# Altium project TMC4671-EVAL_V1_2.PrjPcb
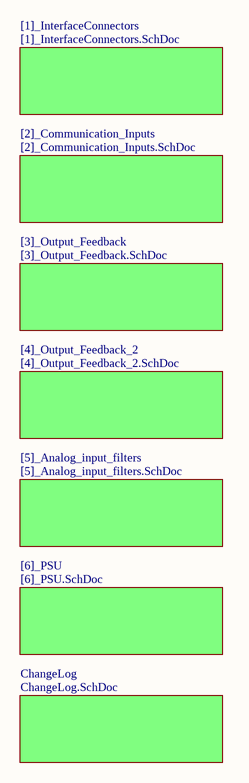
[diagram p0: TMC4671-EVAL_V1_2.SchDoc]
Interfaces: SPI, UART, S/D; Chip: TMCxxx; BoardVersion: 1.2; BoardName: TMC4671-EVAL
8 sheets, 149 parts. Net scope: flat (ports and power ports of the same name join across sheets).
Board file: TMC4671-EVAL_V1_2.PcbDoc
Sheets:
  TMC4671-EVAL_V1_2.SchDoc
    ChangeLog = ChangeLog.SchDoc
    [1]_InterfaceConnectors = [1]_InterfaceConnectors.SchDoc
    [2]_Communication_Inputs = [2]_Communication_Inputs.SchDoc
    [3]_Output_Feedback = [3]_Output_Feedback.SchDoc
    [4]_Output_Feedback_2 = [4]_Output_Feedback_2.SchDoc
    [5]_Analog_input_filters = [5]_Analog_input_filters.SchDoc
    [6]_PSU = [6]_PSU.SchDoc

## Sheet TMC4671-EVAL_V1_2.SchDoc: TMC4671_EVAL_V1.0
size A4; DocumentNumber: 0; SheetNumber: 0; SheetTotal: 8

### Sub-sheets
[1]_InterfaceConnectors = [1]_InterfaceConnectors.SchDoc: no entries
[2]_Communication_Inputs = [2]_Communication_Inputs.SchDoc: no entries
[3]_Output_Feedback = [3]_Output_Feedback.SchDoc: no entries
[4]_Output_Feedback_2 = [4]_Output_Feedback_2.SchDoc: no entries
[5]_Analog_input_filters = [5]_Analog_input_filters.SchDoc: no entries
[6]_PSU = [6]_PSU.SchDoc: no entries
ChangeLog = ChangeLog.SchDoc: no entries

## Sheet ChangeLog.SchDoc: ChangeLog
size A4; DocumentNumber: 7; SheetNumber: 7; SheetTotal: 8
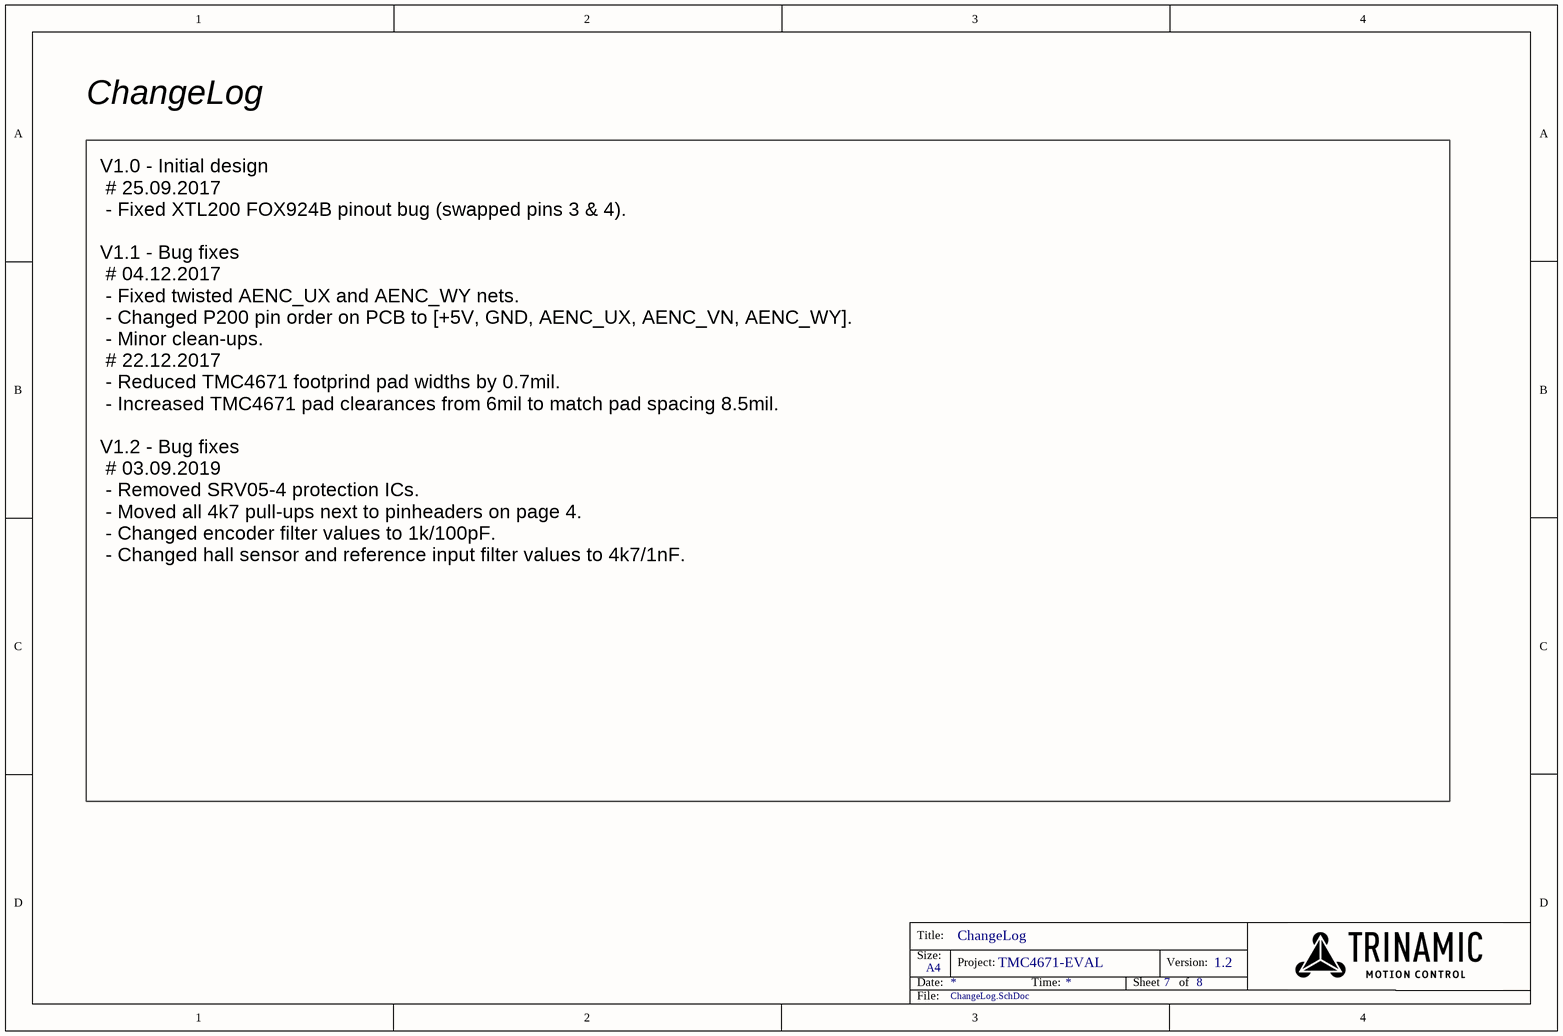
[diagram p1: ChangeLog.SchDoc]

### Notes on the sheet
- ChangeLog
- V1.0 - Initial design
  # 25.09.2017
  - Fixed XTL200 FOX924B pinout bug (swapped pins 3 & 4).
  V1.1 - Bug fixes
  # 04.12.2017
  - Fixed twisted AENC_UX and AENC_WY nets.
  - Changed P200 pin order on PCB to [+5V, GND, AENC_UX, AENC_VN, AENC_WY].
  - Minor clean-ups.
  # 22.12.2017
  - Reduced TMC4671 footprind pad widths by 0.7mil.
  - Increased TMC4671 pad clearances from 6mil to match pad spacing 8.5mil.
  V1.2 - Bug fixes
  # 03.09.2019
  - Removed SRV05-4 protection ICs.
  - Moved all 4k7 pull-ups next to pinheaders on page 4.
  - Changed encoder filter values to 1k/100pF.
  - Changed hall sensor and reference input filter values to 4k7/1nF.

## Sheet [1]_InterfaceConnectors.SchDoc: Interface connectors, mounting holes & testpads
size A4; DocumentNumber: 1; SheetNumber: 1; SheetTotal: 8
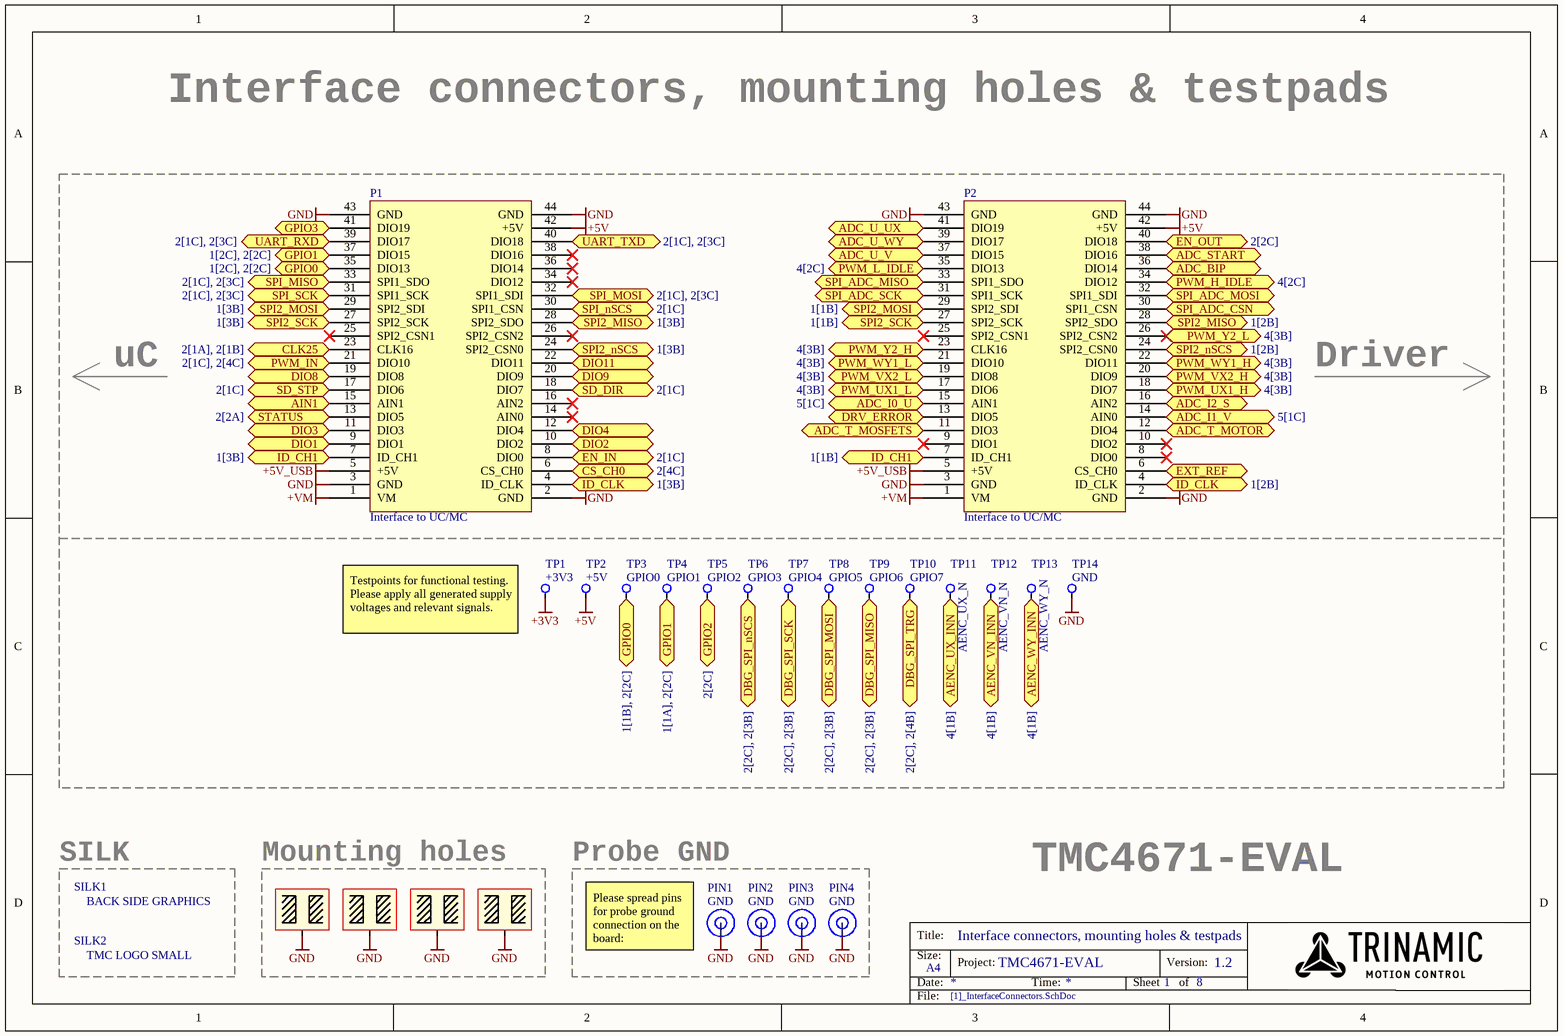
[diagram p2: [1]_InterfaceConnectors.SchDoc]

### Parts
MNT1  MOUNTING_HOLE  [MNT_HOLE_6.35-3.2]  (value not drawn)  (no BOM)
MNT2  MOUNTING_HOLE  [MNT_HOLE_6.35-3.2]  (value not drawn)  (no BOM)
MNT3  MOUNTING_HOLE  [MNT_HOLE_6.35-3.2]  (value not drawn)  (no BOM)
MNT4  MOUNTING_HOLE  [MNT_HOLE_6.35-3.2]  (value not drawn)  (no BOM)
P1  Interface to UC/MC  [Interface_Connector]
P2  Interface to UC/MC  [Interface_Connector]
PIN1  GND  [TP_1.1-1.85_OCT]  (no BOM)
PIN2  GND  [TP_1.1-1.85_OCT]  (no BOM)
PIN3  GND  [TP_1.1-1.85_OCT]  (no BOM)
PIN4  GND  [TP_1.1-1.85_OCT]  (no BOM)
SILK1  BACK SIDE GRAPHICS  [TMC4671_EVAL_v1_0_back_label]  (no BOM)
SILK2  TMC LOGO SMALL  [TMC_logo_small]  (no BOM)
TP1  +3V3  [TP_SMD_1.2MM_ROUND]  (no BOM)
TP2  +5V  [TP_SMD_1.2MM_ROUND]  (no BOM)
TP3  GPIO0  [TP_SMD_1.2MM_ROUND]  (no BOM)
TP4  GPIO1  [TP_SMD_1.2MM_ROUND]  (no BOM)
TP5  GPIO2  [TP_SMD_1.2MM_ROUND]  (no BOM)
TP6  GPIO3  [TP_SMD_1.2MM_ROUND]  (no BOM)
TP7  GPIO4  [TP_SMD_1.2MM_ROUND]  (no BOM)
TP8  GPIO5  [TP_SMD_1.2MM_ROUND]  (no BOM)
TP9  GPIO6  [TP_SMD_1.2MM_ROUND]  (no BOM)
TP10  GPIO7  [TP_SMD_1.2MM_ROUND]  (no BOM)
TP11  AENC_UX_N  [TP_SMD_1.2MM_ROUND]  (no BOM)
TP12  AENC_VN_N  [TP_SMD_1.2MM_ROUND]  (no BOM)
TP13  AENC_WY_N  [TP_SMD_1.2MM_ROUND]  (no BOM)
TP14  GND  [TP_SMD_1.2MM_ROUND]  (no BOM)

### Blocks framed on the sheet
SILK: SILK1 SILK2
Mounting holes: MNT1-MNT4
Probe GND: PIN1-PIN4

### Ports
ADC_BIP, ADC_I0_U (see 5[1C]), ADC_I1_V (see 5[1C]), ADC_I2_S, ADC_START, ADC_T_MOSFETS, ADC_T_MOTOR, ADC_U_UX, ADC_U_V, ADC_U_WY, AENC_UX_INN (see 4[1B]), AENC_VN_INN (see 4[1B]), AENC_WY_INN (see 4[1B]), AIN1, CLK25 (see 2[1A], 2[1B]), CS_CH0 (see 2[4C]), DBG_SPI_MISO (see 2[2C], 2[3B]), DBG_SPI_MOSI (see 2[2C], 2[3B]), DBG_SPI_nSCS (see 2[2C], 2[3B]), DBG_SPI_SCK (see 2[2C], 2[3B]), DBG_SPI_TRG (see 2[2C], 2[4B]), DIO1, DIO2, DIO3, DIO4, DIO8, DIO9, DIO11, DRV_ERROR, EN_IN (see 2[1C]), EN_OUT (see 2[2C]), EXT_REF, GPIO0 (see 1[1B], 2[2C]), GPIO0 (see 1[2C], 2[2C]), GPIO1 (see 1[1A], 2[2C]), GPIO1 (see 1[2C], 2[2C]), GPIO2 (see 2[2C]), GPIO3, ID_CH1 (see 1[1B]), ID_CH1 (see 1[3B]), ID_CLK (see 1[2B]), ID_CLK (see 1[3B]), PWM_H_IDLE (see 4[2C]), PWM_IN (see 2[1C], 2[4C]), PWM_L_IDLE (see 4[2C]), PWM_UX1_H (see 4[3B]), PWM_UX1_L (see 4[3B]), PWM_VX2_H (see 4[3B]), PWM_VX2_L (see 4[3B]), PWM_WY1_H (see 4[3B]), PWM_WY1_L (see 4[3B]), PWM_Y2_H (see 4[3B]), PWM_Y2_L (see 4[3B]), SD_DIR (see 2[1C]), SD_STP (see 2[1C]), SPI2_MISO (see 1[2B]), SPI2_MISO (see 1[3B]), SPI2_MOSI (see 1[1B]), SPI2_MOSI (see 1[3B]), SPI2_nSCS (see 1[2B]), SPI2_nSCS (see 1[3B]), SPI2_SCK (see 1[1B]), SPI2_SCK (see 1[3B]), SPI_ADC_CSN, SPI_ADC_MISO, SPI_ADC_MOSI, SPI_ADC_SCK, SPI_MISO (see 2[1C], 2[3C]), SPI_MOSI (see 2[1C], 2[3C]), SPI_nSCS (see 2[1C]), SPI_SCK (see 2[1C], 2[3C]), STATUS (see 2[2A]), UART_RXD (see 2[1C], 2[3C]), UART_TXD (see 2[1C], 2[3C])

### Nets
+3V3: TP1.1
+5V: P1.42(+5V) P2.42(+5V) TP2.1
+5V_USB: P1.5(+5V) P2.5(+5V)
+VM: P1.1(VM) P2.1(VM)
GND: MNT1.1 MNT2.1 MNT3.1 MNT4.1 P1.2(GND) P1.3(GND) P1.43(GND) P1.44(GND) P2.2(GND) P2.3(GND) P2.43(GND) P2.44(GND) PIN1.1 PIN2.1 PIN3.1 PIN4.1 TP14.1
ADC_BIP: P2.36(DIO14) ; port ADC_BIP
ADC_I0_U: P2.15(AIN1) ; port ADC_I0_U
ADC_I1_V: P2.14(AIN0) ; port ADC_I1_V
ADC_I2_S: P2.16(AIN2) ; port ADC_I2_S
ADC_START: P2.38(DIO16) ; port ADC_START
ADC_T_MOSFETS: P2.11(DIO3) ; port ADC_T_MOSFETS
ADC_T_MOTOR: P2.12(DIO4) ; port ADC_T_MOTOR
ADC_U_UX: P2.41(DIO19) ; port ADC_U_UX
ADC_U_V: P2.37(DIO15) ; port ADC_U_V
ADC_U_WY: P2.39(DIO17) ; port ADC_U_WY
AENC_UX_INN: TP11.1 ; port AENC_UX_INN
AENC_VN_INN: TP12.1 ; port AENC_VN_INN
AENC_WY_INN: TP13.1 ; port AENC_WY_INN
AIN1: P1.15(AIN1) ; port AIN1
CLK25: P1.23(CLK16) ; port CLK25
CS_CH0: P1.6(CS_CH0) ; port CS_CH0
DBG_SPI_MISO: TP9.1 ; port DBG_SPI_MISO
DBG_SPI_MOSI: TP8.1 ; port DBG_SPI_MOSI
DBG_SPI_nSCS: TP6.1 ; port DBG_SPI_nSCS
DBG_SPI_SCK: TP7.1 ; port DBG_SPI_SCK
DBG_SPI_TRG: TP10.1 ; port DBG_SPI_TRG
DIO1: P1.9(DIO1) ; port DIO1
DIO2: P1.10(DIO2) ; port DIO2
DIO3: P1.11(DIO3) ; port DIO3
DIO4: P1.12(DIO4) ; port DIO4
DIO8: P1.19(DIO8) ; port DIO8
DIO9: P1.20(DIO9) ; port DIO9
DIO11: P1.22(DIO11) ; port DIO11
DRV_ERROR: P2.13(DIO5) ; port DRV_ERROR
EN_IN: P1.8(DIO0) ; port EN_IN
EN_OUT: P2.40(DIO18) ; port EN_OUT
EXT_REF: P2.6(CS_CH0) ; port EXT_REF
GPIO0: P1.35(DIO13) TP3.1 ; port GPIO0
GPIO1: P1.37(DIO15) TP4.1 ; port GPIO1
GPIO2: TP5.1 ; port GPIO2
GPIO3: P1.41(DIO19) ; port GPIO3
ID_CH1: P1.7(ID_CH1) P2.7(ID_CH1) ; port ID_CH1
ID_CLK: P1.4(ID_CLK) P2.4(ID_CLK) ; port ID_CLK
PWM_H_IDLE: P2.34(DIO12) ; port PWM_H_IDLE
PWM_IN: P1.21(DIO10) ; port PWM_IN
PWM_L_IDLE: P2.35(DIO13) ; port PWM_L_IDLE
PWM_UX1_H: P2.18(DIO7) ; port PWM_UX1_H
PWM_UX1_L: P2.17(DIO6) ; port PWM_UX1_L
PWM_VX2_H: P2.20(DIO9) ; port PWM_VX2_H
PWM_VX2_L: P2.19(DIO8) ; port PWM_VX2_L
PWM_WY1_H: P2.22(DIO11) ; port PWM_WY1_H
PWM_WY1_L: P2.21(DIO10) ; port PWM_WY1_L
PWM_Y2_H: P2.23(CLK16) ; port PWM_Y2_H
PWM_Y2_L: P2.26(SPI2_CSN2) ; port PWM_Y2_L
SD_DIR: P1.18(DIO7) ; port SD_DIR
SD_STP: P1.17(DIO6) ; port SD_STP
SPI2_MISO: P1.28(SPI2_SDO) P2.28(SPI2_SDO) ; port SPI2_MISO
SPI2_MOSI: P1.29(SPI2_SDI) P2.29(SPI2_SDI) ; port SPI2_MOSI
SPI2_nSCS: P1.24(SPI2_CSN0) P2.24(SPI2_CSN0) ; port SPI2_nSCS
SPI2_SCK: P1.27(SPI2_SCK) P2.27(SPI2_SCK) ; port SPI2_SCK
SPI_ADC_CSN: P2.30(SPI1_CSN) ; port SPI_ADC_CSN
SPI_ADC_MISO: P2.33(SPI1_SDO) ; port SPI_ADC_MISO
SPI_ADC_MOSI: P2.32(SPI1_SDI) ; port SPI_ADC_MOSI
SPI_ADC_SCK: P2.31(SPI1_SCK) ; port SPI_ADC_SCK
SPI_MISO: P1.33(SPI1_SDO) ; port SPI_MISO
SPI_MOSI: P1.32(SPI1_SDI) ; port SPI_MOSI
SPI_nSCS: P1.30(SPI1_CSN) ; port SPI_nSCS
SPI_SCK: P1.31(SPI1_SCK) ; port SPI_SCK
STATUS: P1.13(DIO5) ; port STATUS
UART_RXD: P1.39(DIO17) ; port UART_RXD
UART_TXD: P1.40(DIO18) ; port UART_TXD

Not connected (* = marked no-connect by the designer): P1 14(AIN0)* 16(AIN2)* 25(SPI2_CSN1)* 26(SPI2_CSN2)* 34(DIO12)* 36(DIO14)* 38(DIO16)*; P2 8(DIO0)* 9(DIO1)* 10(DIO2)* 25(SPI2_CSN1)*

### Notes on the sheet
- uC
- Driver
- (near TP1) Testpoints for functional testing.
  Please apply all generated supply voltages and relevant signals.
- (near PIN1) Please spread pins for probe ground connection on the board:

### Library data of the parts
P1 P2 = Interface Connector, 44 Pins: Board-To-Board Connector, 2.54 mm, 44 Contacts, Receptacle, HLE Series, Surface Mount, 2 Rows; MPN: HLE-122-02-L-DV; MF: SAMTEC
PIN1-PIN4 = TP_1.1-1.85_OCT: TH testpoint, 1.1 hole, 1.85 pad, octagonal
SILK1 SILK2 = SILK_GFX
TP1-TP14 = TP_SMD_Xmm: SMD testpoint, 1.2mm pad, round

## Sheet [2]_Communication_Inputs.SchDoc: Communication & Inputs
size A4; DocumentNumber: 2; SheetNumber: 2; SheetTotal: 8
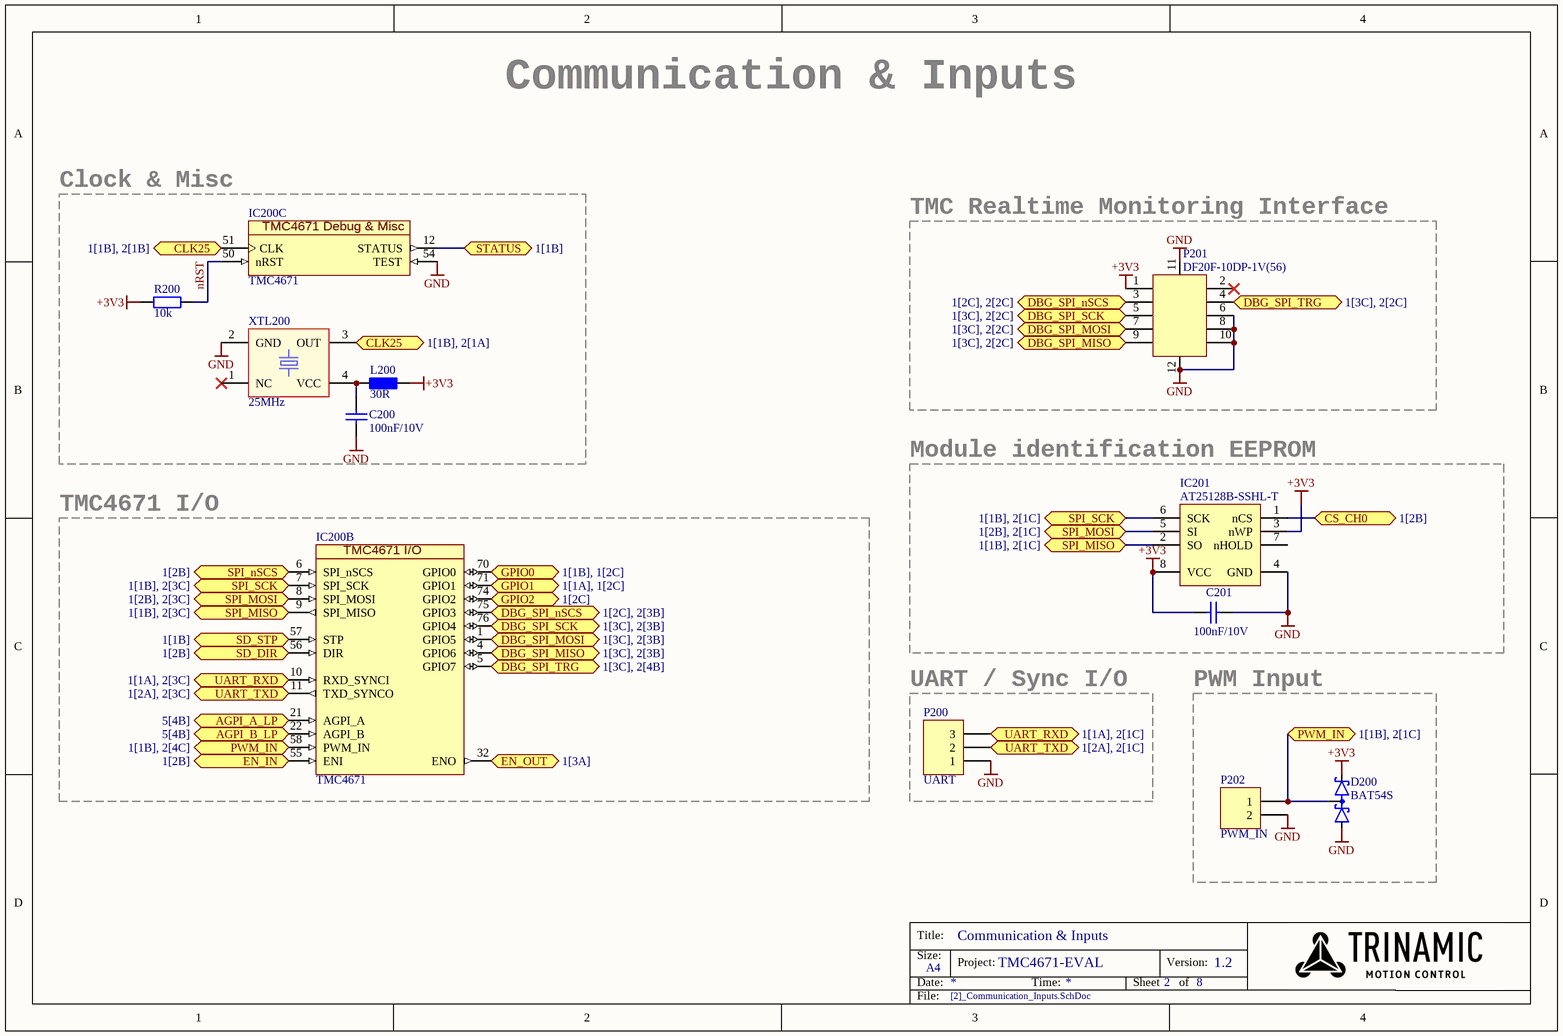
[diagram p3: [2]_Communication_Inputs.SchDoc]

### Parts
C200  100nF/10V  [C0603]
C201  100nF/10V  [C0603]
D200  BAT54S  [SOT95P237X130-3N]
IC200  TMC4671  [QFN40P1050X650X90_HS-77N]  (parts B,C of 5)
IC201  AT25128B-SSHL-T  [SOP127P600X175-8N]
L200  30R  [L0603]
P200  UART  [TH_HDR_1X3]
P201  DF20F-10DP-1V(56)  [CON, TMC Debug SPI]
P202  PWM_IN  [TH_HDR_1X2]
R200  10k  [R0603]
XTL200  25MHz  [FOX924B-25.000]

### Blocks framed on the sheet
Clock & Misc: C200 IC200 L200 R200 XTL200
TMC Realtime Monitoring Interface: P201
TMC4671 I/O: IC200
Module identification EEPROM: C201 IC201
UART / Sync I/O: P200
PWM Input: D200 P202

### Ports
AGPI_A_LP (see 5[4B]), AGPI_B_LP (see 5[4B]), CLK25 (see 1[1B], 2[1A]), CLK25 (see 1[1B], 2[1B]), CS_CH0 (see 1[2B]), DBG_SPI_MISO (see 1[3C], 2[2C]), DBG_SPI_MISO (see 1[3C], 2[3B]), DBG_SPI_MOSI (see 1[3C], 2[2C]), DBG_SPI_MOSI (see 1[3C], 2[3B]), DBG_SPI_nSCS (see 1[2C], 2[2C]), DBG_SPI_nSCS (see 1[2C], 2[3B]), DBG_SPI_SCK (see 1[3C], 2[2C]), DBG_SPI_SCK (see 1[3C], 2[3B]), DBG_SPI_TRG (see 1[3C], 2[2C]), DBG_SPI_TRG (see 1[3C], 2[4B]), EN_IN (see 1[2B]), EN_OUT (see 1[3A]), GPIO0 (see 1[1B], 1[2C]), GPIO1 (see 1[1A], 1[2C]), GPIO2 (see 1[2C]), PWM_IN (see 1[1B], 2[1C]), PWM_IN (see 1[1B], 2[4C]), SD_DIR (see 1[2B]), SD_STP (see 1[1B]), SPI_MISO (see 1[1B], 2[1C]), SPI_MISO (see 1[1B], 2[3C]), SPI_MOSI (see 1[2B], 2[1C]), SPI_MOSI (see 1[2B], 2[3C]), SPI_nSCS (see 1[2B]), SPI_SCK (see 1[1B], 2[1C]), SPI_SCK (see 1[1B], 2[3C]), STATUS (see 1[1B]), UART_RXD (see 1[1A], 2[1C]), UART_RXD (see 1[1A], 2[3C]), UART_TXD (see 1[2A], 2[1C]), UART_TXD (see 1[2A], 2[3C])

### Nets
+3V3: C201.2 D200.2(C2) IC201.3(nWP) IC201.8(VCC) L200.1 P201.1 R200.2
GND: C200.2 C201.1 D200.1(A1) IC200.54(TEST) IC201.4(GND) P200.1 P201.6 P201.8 P201.10 P201.11 P201.12 P202.2 XTL200.2(GND)
AGPI_A_LP: IC200.21(AGPI_A) ; port AGPI_A_LP
AGPI_B_LP: IC200.22(AGPI_B) ; port AGPI_B_LP
CLK25: IC200.51(CLK) XTL200.3(OUT) ; port CLK25
CS_CH0: IC201.1(nCS) ; port CS_CH0
DBG_SPI_MISO: IC200.4(GPIO6) P201.9 ; port DBG_SPI_MISO
DBG_SPI_MOSI: IC200.1(GPIO5) P201.7 ; port DBG_SPI_MOSI
DBG_SPI_nSCS: IC200.75(GPIO3) P201.3 ; port DBG_SPI_nSCS
DBG_SPI_SCK: IC200.76(GPIO4) P201.5 ; port DBG_SPI_SCK
DBG_SPI_TRG: IC200.5(GPIO7) P201.4 ; port DBG_SPI_TRG
EN_IN: IC200.55(ENI) ; port EN_IN
EN_OUT: IC200.32(ENO) ; port EN_OUT
GPIO0: IC200.70(GPIO0) ; port GPIO0
GPIO1: IC200.71(GPIO1) ; port GPIO1
GPIO2: IC200.74(GPIO2) ; port GPIO2
nRST: IC200.50(nRST) R200.1
PWM_IN: D200.3(C1A2) IC200.58(PWM_IN) P202.1 ; port PWM_IN
SD_DIR: IC200.56(DIR) ; port SD_DIR
SD_STP: IC200.57(STP) ; port SD_STP
SPI_MISO: IC200.9(SPI_MISO) IC201.2(SO) ; port SPI_MISO
SPI_MOSI: IC200.8(SPI_MOSI) IC201.5(SI) ; port SPI_MOSI
SPI_nSCS: IC200.6(SPI_nSCS) ; port SPI_nSCS
SPI_SCK: IC200.7(SPI_SCK) IC201.6(SCK) ; port SPI_SCK
STATUS: IC200.12(STATUS) ; port STATUS
UART_RXD: IC200.10(RXD_SYNCI) P200.3 ; port UART_RXD
UART_TXD: IC200.11(TXD_SYNCO) P200.2 ; port UART_TXD
NetC200_1: C200.1 L200.2 XTL200.4(VCC)

Not connected (* = marked no-connect by the designer): IC201 7(nHOLD); P201 2*; XTL200 1(NC)*

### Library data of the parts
C200 C201 = C, 0.1 µF, 10 V, ± 10%, X7R, 0603: SMD Multilayer Ceramic Capacitor, 0603 [1608 Metric], 0.1 µF, 10 V, ± 10%, X7R, MC Series; MPN: MC0603B104K100CT; Type: MLCC; VoltageRating: 10V; MF: Multicomp; Capacitance: 100nF
D200 = BAT54S: Small Signal Schottky Diode, Dual Series, 30 V, 200 mA, 1 V, 600 mA, 125 °C; MF: TAIWAN SEMICONDUCTOR
IC200 = TMC4671: MF: TRINAMIC
IC201 = EEPROM_ AT25128B-SSHL-T: EEPROM, SPI, 128 Kbit, 16K x 8bit, 20 MHz, SOIC, 8 Pins; MF: MICROCHIP
L200 = FB, 30 ohm, 0603 [1608 Metric], MFB Series, 3 A, 0.04 ohm, ± 25%: Ferrite Bead, 30 ohm, 0603 [1608 Metric], MFB Series, 3 A, 0.04 ohm, ± 25%; MPN: MFB-160808-0030PQ; MF: MEC MARCOM; DC Current Rating: 3A; DC Resistance Max:: 0R04
P200 = Header 3: Header, 3-Pin; Note: Not fitted
P201 = CON, TMC Debug SPI: Wire-To-Board Connector, 1 mm, 10 Contacts, Header, DF20 Series, Surface Mount, 2 Rows; MF: Hirose Electric Co Ltd
P202 = Header 2: Header, 2-Pin; Note: Not fitted
R200 = R, 10 kohm, 50 V, 0603 [1608 Metric], 63 mW, ± 1%, MC Series: SMD Chip Resistor, Thick Film, 10 kohm, 50 V, 0603 [1608 Metric], 63 mW, ± 1%, MC Series; MPN: MC0063W0603110K; VoltageRating: 50V; Temp coefficient: *ppm; PowerRating: 63mW; MF: MULTICOMP
XTL200 = 25 MHz, 2.5 ppm, SMD, 5mm x 3.2mm, HCMOS, 3.3 V, FOX924 Series: TCXO, 25 MHz, 2.5 ppm, SMD, 5mm x 3.2mm, HCMOS, 3.3 V, FOX924 Series; MF: FOX ELECTRONICS; Freq. Stability: 2.5ppm; Op.temp.: -30°C...+80°C

## Sheet [3]_Output_Feedback.SchDoc: Output & Feedback
size A4 portrait; DocumentNumber: 3; SheetNumber: 3; SheetTotal: 8
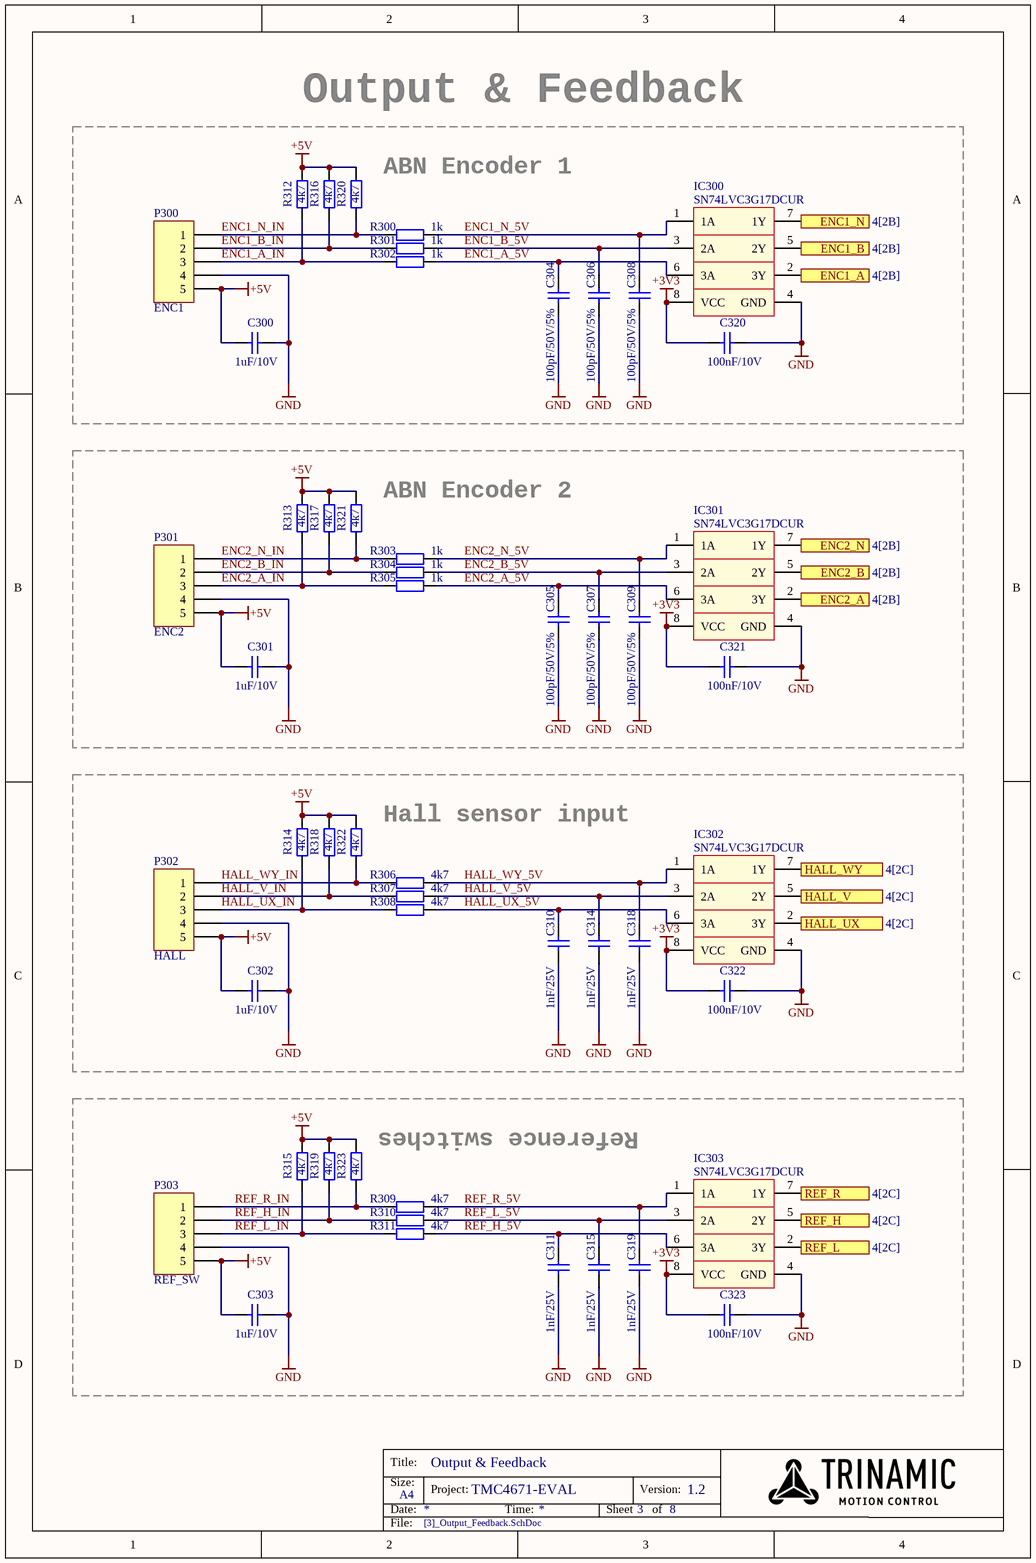
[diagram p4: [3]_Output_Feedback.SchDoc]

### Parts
C300  1uF/10V  [C0603]
C301  1uF/10V  [C0603]
C302  1uF/10V  [C0603]
C303  1uF/10V  [C0603]
C304  100pF/50V/5%  [C0603]
C305  100pF/50V/5%  [C0603]
C306  100pF/50V/5%  [C0603]
C307  100pF/50V/5%  [C0603]
C308  100pF/50V/5%  [C0603]
C309  100pF/50V/5%  [C0603]
C310  1nF/25V  [C0603]
C311  1nF/25V  [C0603]
C314  1nF/25V  [C0603]
C315  1nF/25V  [C0603]
C318  1nF/25V  [C0603]
C319  1nF/25V  [C0603]
C320  100nF/10V  [C0603]
C321  100nF/10V  [C0603]
C322  100nF/10V  [C0603]
C323  100nF/10V  [C0603]
IC300  SN74LVC3G17DCUR  [TSSOP50P310X90-8L]
IC301  SN74LVC3G17DCUR  [TSSOP50P310X90-8L]
IC302  SN74LVC3G17DCUR  [TSSOP50P310X90-8L]
IC303  SN74LVC3G17DCUR  [TSSOP50P310X90-8L]
P300  ENC1  [TH_HDR_1X5]
P301  ENC2  [TH_HDR_1X5]
P302  HALL  [TH_HDR_1X5]
P303  REF_SW  [TH_HDR_1X5]
R300  1k  [R0603]
R301  1k  [R0603]
R302  1k  [R0603]
R303  1k  [R0603]
R304  1k  [R0603]
R305  1k  [R0603]
R306  4k7  [R0603]
R307  4k7  [R0603]
R308  4k7  [R0603]
R309  4k7  [R0603]
R310  4k7  [R0603]
R311  4k7  [R0603]
R312  4k7  [R0603]
R313  4k7  [R0603]
R314  4k7  [R0603]
R315  4k7  [R0603]
R316  4k7  [R0603]
R317  4k7  [R0603]
R318  4k7  [R0603]
R319  4k7  [R0603]
R320  4k7  [R0603]
R321  4k7  [R0603]
R322  4k7  [R0603]
R323  4k7  [R0603]

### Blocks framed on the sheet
ABN Encoder 1: C300 C304 C306 C308 C320 IC300 P300 R300-R302 R312 R316 R320
ABN Encoder 2: C301 C305 C307 C309 C321 IC301 P301 R303-R305 R313 R317 R321
Hall sensor input: C302 C310 C314 C318 C322 IC302 P302 R306-R308 R314 R318 R322
Reference switches: C303 C311 C315 C319 C323 IC303 P303 R309-R311 R315 R319 R323

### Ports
ENC1_A (see 4[2B]), ENC1_B (see 4[2B]), ENC1_N (see 4[2B]), ENC2_A (see 4[2B]), ENC2_B (see 4[2B]), ENC2_N (see 4[2B]), HALL_UX (see 4[2C]), HALL_V (see 4[2C]), HALL_WY (see 4[2C]), REF_H (see 4[2C]), REF_L (see 4[2C]), REF_R (see 4[2C])

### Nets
+3V3: C320.2 C321.2 C322.2 C323.2 IC300.8(VCC) IC301.8(VCC) IC302.8(VCC) IC303.8(VCC)
+5V: C300.2 C301.2 C302.2 C303.2 P300.5 P301.5 P302.5 P303.5 R312.2 R313.2 R314.2 R315.2 R316.2 R317.2 R318.2 R319.2 R320.2 R321.2 R322.2 R323.2
GND: C300.1 C301.1 C302.1 C303.1 C304.1 C305.1 C306.1 C307.1 C308.1 C309.1 C310.1 C311.1 C314.1 C315.1 C318.1 C319.1 C320.1 C321.1 C322.1 C323.1 IC300.4(GND) IC301.4(GND) IC302.4(GND) IC303.4(GND) P300.4 P301.4 P302.4 P303.4
ENC1_A: IC300.2(3Y) ; port ENC1_A
ENC1_A_5V: C304.2 IC300.6(3A) R302.2
ENC1_A_IN: P300.3 R302.1 R312.1
ENC1_B: IC300.5(2Y) ; port ENC1_B
ENC1_B_5V: C306.2 IC300.3(2A) R301.2
ENC1_B_IN: P300.2 R301.1 R316.1
ENC1_N: IC300.7(1Y) ; port ENC1_N
ENC1_N_5V: C308.2 IC300.1(1A) R300.2
ENC1_N_IN: P300.1 R300.1 R320.1
ENC2_A: IC301.2(3Y) ; port ENC2_A
ENC2_A_5V: C305.2 IC301.6(3A) R305.2
ENC2_A_IN: P301.3 R305.1 R313.1
ENC2_B: IC301.5(2Y) ; port ENC2_B
ENC2_B_5V: C307.2 IC301.3(2A) R304.2
ENC2_B_IN: P301.2 R304.1 R317.1
ENC2_N: IC301.7(1Y) ; port ENC2_N
ENC2_N_5V: C309.2 IC301.1(1A) R303.2
ENC2_N_IN: P301.1 R303.1 R321.1
HALL_UX: IC302.2(3Y) ; port HALL_UX
HALL_UX_5V: C310.2 IC302.6(3A) R308.1
HALL_UX_IN: P302.3 R308.2 R314.1
HALL_V: IC302.5(2Y) ; port HALL_V
HALL_V_5V: C314.2 IC302.3(2A) R307.1
HALL_V_IN: P302.2 R307.2 R318.1
HALL_WY: IC302.7(1Y) ; port HALL_WY
HALL_WY_5V: C318.2 IC302.1(1A) R306.1
HALL_WY_IN: P302.1 R306.2 R322.1
REF_H: IC303.5(2Y) ; port REF_H
REF_H_5V: C311.2 IC303.6(3A) R311.1
REF_H_IN: P303.2 R310.2 R319.1
REF_L: IC303.2(3Y) ; port REF_L
REF_L_5V: C315.2 IC303.3(2A) R310.1
REF_L_IN: P303.3 R311.2 R315.1
REF_R: IC303.7(1Y) ; port REF_R
REF_R_5V: C319.2 IC303.1(1A) R309.1
REF_R_IN: P303.1 R309.2 R323.1

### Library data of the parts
C300-C303 = C, 1 µF, 10 V, ± 10%, X5R, MC Series, 0603 [1608 Metric]: SMD Multilayer Ceramic Capacitor, 0603 [1608 Metric], 1 µF, 10 V, ± 10%, X5R, MC Series; MPN: MC0603X105K100CT; Type: MLCC; VoltageRating: 10V; MF: MULTICOMP; Capacitance: 1uF
C304-C309 = C, 100 pF, 50 V, ± 5%, C0G / NP0, MC Series, 0603 [1608 Metric]: SMD Multilayer Ceramic Capacitor, 0603 [1608 Metric], 100 pF, 50 V, ± 5%, C0G / NP0, MC Series; MPN: MC0603N101J500CT; Type: MLCC; VoltageRating: 50V; MF: MULTICOMP; Capacitance: 100pF
C310 C311 C314 C315 C318 C319 = C, 1nF, 25 V, ± 10%, X7R, MC Series, 0603 [1608 Metric]: SMD Multilayer Ceramic Capacitor, 0603 [1608 Metric], 1000 pF, 25 V, ± 10%, X7R, MC Series; MPN: MC0603B102K250CT; Type: MLCC; VoltageRating: 25V; MF: MULTICOMP; Capacitance: 1nF
C320-C323 = C, 0.1 µF, 10 V, ± 10%, X7R, 0603: as C200 on sheet [2]_Communication_Inputs
IC300-IC303 = SN74LVC3G17DCUR: Triple Schmitt-Trigger Buffer, 74LVC3G17, 1.65 V to 5.5 V, VSSOP-8; MF: TEXAS INSTRUMENTS
P300-P303 = Header 5: Header, 5-Pin
R300-R305 = R, 1 kohm, 50 V, 0603 [1608 Metric], 100mW, ± 1%, MCWR Series: SMD Chip Resistor, Thick Film, 1 kohm, 50 V, 0603 [1608 Metric], 100 mW, ± 1%, MCWR Series; MPN: MCWR06X1001FTL; VoltageRating: 50V; Temp coefficient: *ppm; PowerRating: 100mW; MF: MULTICOMP
R306-R323 = R, 4.7 kohm, 75 V, 0603 [1608 Metric], 100 mW, ± 1%, WR06 Series: SMD Chip Resistor, 4.7 kohm, 75 V, 0603 [1608 Metric], 100 mW, ± 1%, WR06 Series; MPN: WR06X4701FTL; VoltageRating: 75V; Temp coefficient: *ppm; PowerRating: 100mW; MF: WALSIN

## Sheet [4]_Output_Feedback_2.SchDoc: Output & Feedback 2
size A4; DocumentNumber: 4; SheetNumber: 4; SheetTotal: 8
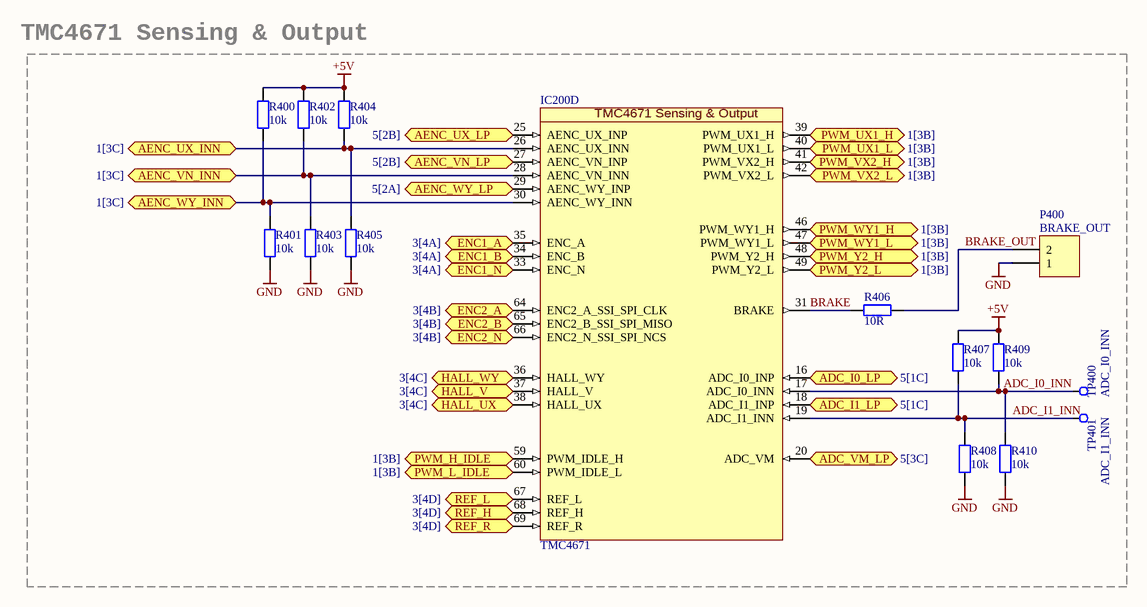
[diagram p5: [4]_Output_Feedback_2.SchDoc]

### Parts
IC200  TMC4671  [QFN40P1050X650X90_HS-77N]  (part D of 5)
P400  BRAKE_OUT  [TH_HDR_1X2]
R400  10k  [R0603]
R401  10k  [R0603]
R402  10k  [R0603]
R403  10k  [R0603]
R404  10k  [R0603]
R405  10k  [R0603]
R406  10R  [R0603]
R407  10k  [R0603]
R408  10k  [R0603]
R409  10k  [R0603]
R410  10k  [R0603]
TP400  ADC_I0_INN  [TP_SMD_1.2MM_ROUND]  (no BOM)
TP401  ADC_I1_INN  [TP_SMD_1.2MM_ROUND]  (no BOM)

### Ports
ADC_I0_LP (see 5[1C]), ADC_I1_LP (see 5[1C]), ADC_VM_LP (in, see 5[3C]), AENC_UX_INN (see 1[3C]), AENC_UX_LP (see 5[2B]), AENC_VN_INN (see 1[3C]), AENC_VN_LP (see 5[2B]), AENC_WY_INN (see 1[3C]), AENC_WY_LP (see 5[2A]), ENC1_A (see 3[4A]), ENC1_B (see 3[4A]), ENC1_N (see 3[4A]), ENC2_A (see 3[4B]), ENC2_B (see 3[4B]), ENC2_N (see 3[4B]), HALL_UX (see 3[4C]), HALL_V (see 3[4C]), HALL_WY (see 3[4C]), PWM_H_IDLE (see 1[3B]), PWM_L_IDLE (see 1[3B]), PWM_UX1_H (see 1[3B]), PWM_UX1_L (see 1[3B]), PWM_VX2_H (see 1[3B]), PWM_VX2_L (see 1[3B]), PWM_WY1_H (see 1[3B]), PWM_WY1_L (see 1[3B]), PWM_Y2_H (see 1[3B]), PWM_Y2_L (see 1[3B]), REF_H (see 3[4D]), REF_L (see 3[4D]), REF_R (see 3[4D])

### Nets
+5V: R400.2 R402.2 R404.2 R407.2 R409.2
GND: P400.1 R401.1 R403.1 R405.1 R408.1 R410.1
ADC_I0_INN: IC200.17(ADC_I0_INN) R409.1 R410.2 TP400.1
ADC_I0_LP: IC200.16(ADC_I0_INP) ; port ADC_I0_LP
ADC_I1_INN: IC200.19(ADC_I1_INN) R407.1 R408.2 TP401.1
ADC_I1_LP: IC200.18(ADC_I1_INP) ; port ADC_I1_LP
ADC_VM_LP: IC200.20(ADC_VM) ; port ADC_VM_LP
AENC_UX_INN: IC200.26(AENC_UX_INN) R404.1 R405.2 ; port AENC_UX_INN
AENC_UX_LP: IC200.25(AENC_UX_INP) ; port AENC_UX_LP
AENC_VN_INN: IC200.28(AENC_VN_INN) R402.1 R403.2 ; port AENC_VN_INN
AENC_VN_LP: IC200.27(AENC_VN_INP) ; port AENC_VN_LP
AENC_WY_INN: IC200.30(AENC_WY_INN) R400.1 R401.2 ; port AENC_WY_INN
AENC_WY_LP: IC200.29(AENC_WY_INP) ; port AENC_WY_LP
BRAKE: IC200.31(BRAKE) R406.2
BRAKE_OUT: P400.2 R406.1
ENC1_A: IC200.35(ENC_A) ; port ENC1_A
ENC1_B: IC200.34(ENC_B) ; port ENC1_B
ENC1_N: IC200.33(ENC_N) ; port ENC1_N
ENC2_A: IC200.64(ENC2_A_SSI_SPI_CLK) ; port ENC2_A
ENC2_B: IC200.65(ENC2_B_SSI_SPI_MISO) ; port ENC2_B
ENC2_N: IC200.66(ENC2_N_SSI_SPI_NCS) ; port ENC2_N
HALL_UX: IC200.38(HALL_UX) ; port HALL_UX
HALL_V: IC200.37(HALL_V) ; port HALL_V
HALL_WY: IC200.36(HALL_WY) ; port HALL_WY
PWM_H_IDLE: IC200.59(PWM_IDLE_H) ; port PWM_H_IDLE
PWM_L_IDLE: IC200.60(PWM_IDLE_L) ; port PWM_L_IDLE
PWM_UX1_H: IC200.39(PWM_UX1_H) ; port PWM_UX1_H
PWM_UX1_L: IC200.40(PWM_UX1_L) ; port PWM_UX1_L
PWM_VX2_H: IC200.41(PWM_VX2_H) ; port PWM_VX2_H
PWM_VX2_L: IC200.42(PWM_VX2_L) ; port PWM_VX2_L
PWM_WY1_H: IC200.46(PWM_WY1_H) ; port PWM_WY1_H
PWM_WY1_L: IC200.47(PWM_WY1_L) ; port PWM_WY1_L
PWM_Y2_H: IC200.48(PWM_Y2_H) ; port PWM_Y2_H
PWM_Y2_L: IC200.49(PWM_Y2_L) ; port PWM_Y2_L
REF_H: IC200.68(REF_H) ; port REF_H
REF_L: IC200.67(REF_L) ; port REF_L
REF_R: IC200.69(REF_R) ; port REF_R

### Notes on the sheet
- TMC4671 Sensing & Output

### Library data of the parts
IC200 = TMC4671: MF: TRINAMIC
P400 = Header 2: Header, 2-Pin
R400-R405 R407-R410 = R, 10 kohm, 50 V, 0603 [1608 Metric], 63 mW, ± 1%, MC Series: as R200 on sheet [2]_Communication_Inputs
R406 = R, 10 ohm, 50 V, 0603 [1608 Metric], 100 mW, ± 1%, MCWR Series: SMD Chip Resistor, Thick Film, 10 ohm, 50 V, 0603 [1608 Metric], 100 mW, ± 1%, MCWR Series; MPN: MC0063W0603110K; VoltageRating: 50V; Temp coefficient: *ppm; PowerRating: 100mW; MF: MULTICOMP
TP400 TP401 = TP_SMD_Xmm: SMD testpoint, 1.2mm pad, round

## Sheet [5]_Analog_input_filters.SchDoc: Analog inputs & filters
size A4; DocumentNumber: 5; SheetNumber: 5; SheetTotal: 8
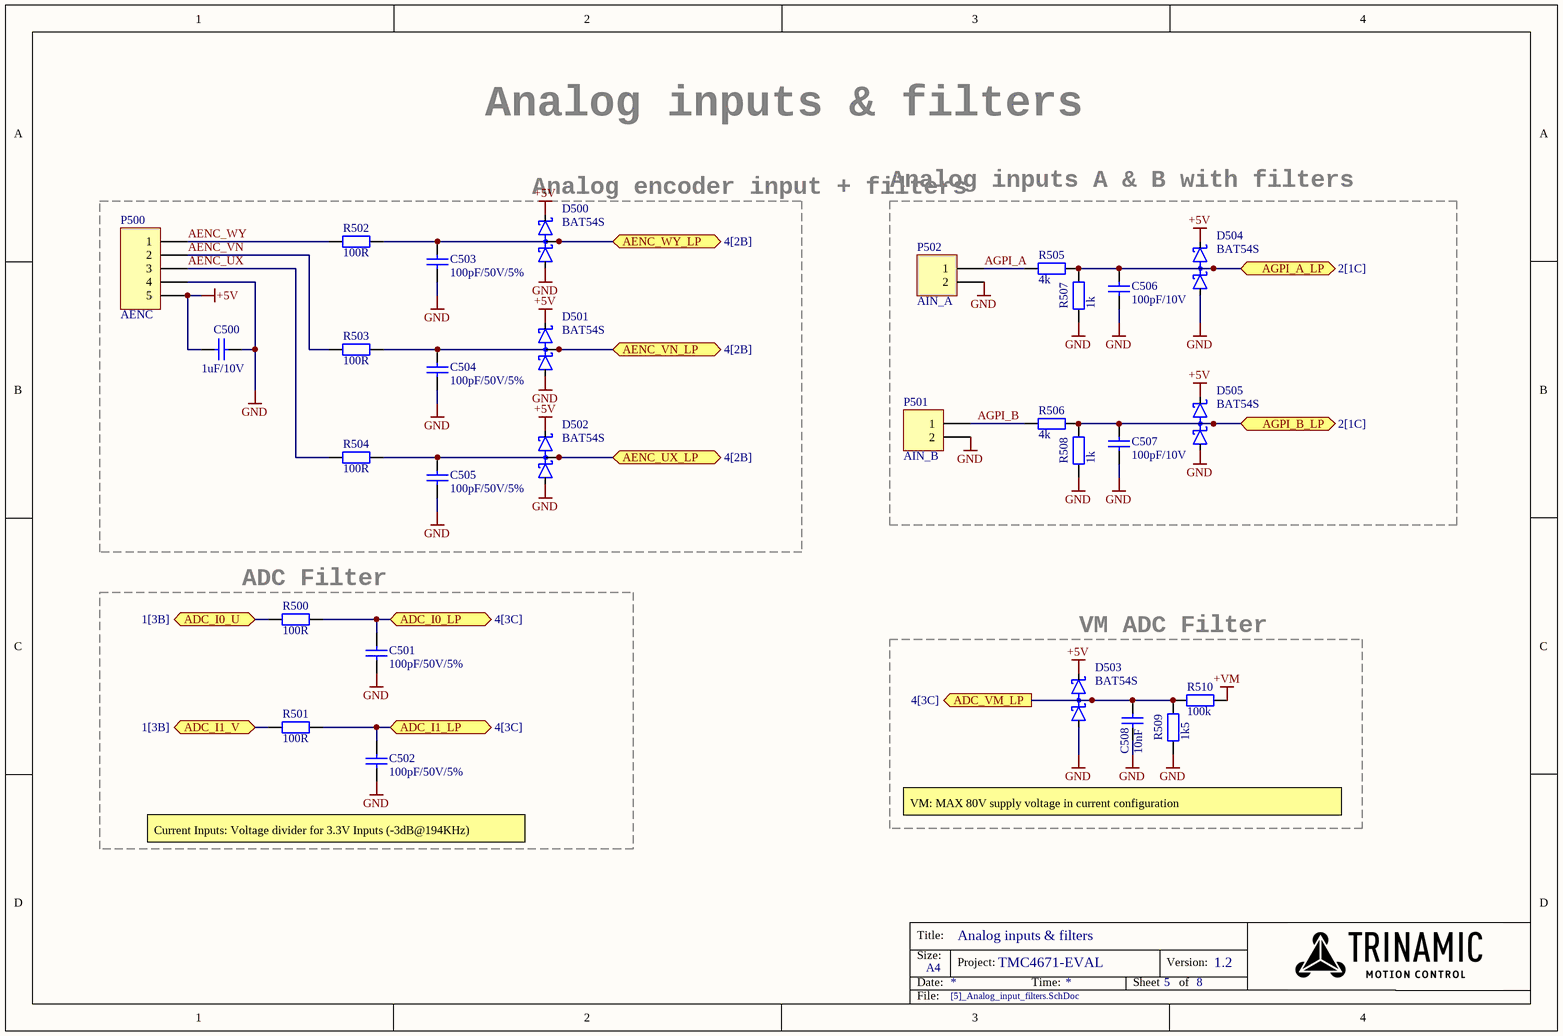
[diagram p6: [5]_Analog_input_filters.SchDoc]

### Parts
C500  1uF/10V  [C0603]
C501  100pF/50V/5%  [C0603]
C502  100pF/50V/5%  [C0603]
C503  100pF/50V/5%  [C0603]
C504  100pF/50V/5%  [C0603]
C505  100pF/50V/5%  [C0603]
C506  100pF/10V  [C0603]
C507  100pF/10V  [C0603]
C508  10nF  [C0603]
D500  BAT54S  [SOT95P237X130-3N]
D501  BAT54S  [SOT95P237X130-3N]
D502  BAT54S  [SOT95P237X130-3N]
D503  BAT54S  [SOT95P237X130-3N]
D504  BAT54S  [SOT95P237X130-3N]
D505  BAT54S  [SOT95P237X130-3N]
P500  AENC  [TH_HDR_1X5]
P501  AIN_B  [TH_HDR_1X2]
P502  AIN_A  [TH_HDR_1X2]
R500  100R  [R0603]
R501  100R  [R0603]
R502  100R  [R0603]
R503  100R  [R0603]
R504  100R  [R0603]
R505  4k  [R0805]
R506  4k  [R0805]
R507  1k  [R0603]
R508  1k  [R0603]
R509  1k5  [R0603]
R510  100k  [R0603]

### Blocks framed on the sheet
Analog encoder input + filters: C500 C503-C505 D500-D502 P500 R502-R504
Analog inputs A & B with filters: C506 C507 D504 D505 P501 P502 R505-R508
ADC Filter: C501 C502 R500 R501

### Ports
ADC_I0_LP (see 4[3C]), ADC_I0_U (see 1[3B]), ADC_I1_LP (see 4[3C]), ADC_I1_V (see 1[3B]), ADC_VM_LP (out, see 4[3C]), AENC_UX_LP (see 4[2B]), AENC_VN_LP (see 4[2B]), AENC_WY_LP (see 4[2B]), AGPI_A_LP (see 2[1C]), AGPI_B_LP (see 2[1C])

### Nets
+5V: C500.2 D500.2(C2) D501.2(C2) D502.2(C2) D503.2(C2) D504.2(C2) D505.2(C2) P500.5
+VM: R510.2
GND: C500.1 C501.1 C502.1 C503.1 C504.1 C505.1 C506.1 C507.1 C508.1 D500.1(A1) D501.1(A1) D502.1(A1) D503.1(A1) D504.1(A1) D505.1(A1) P500.4 P501.2 P502.2 R507.2 R508.2 R509.2
ADC_I0_LP: C501.2 R500.1 ; port ADC_I0_LP
ADC_I0_U: R500.2 ; port ADC_I0_U
ADC_I1_LP: C502.2 R501.1 ; port ADC_I1_LP
ADC_I1_V: R501.2 ; port ADC_I1_V
ADC_VM_LP: C508.2 D503.3(C1A2) R509.1 R510.1 ; port ADC_VM_LP
AENC_UX: P500.3 R504.2
AENC_UX_LP: C505.2 D502.3(C1A2) R504.1 ; port AENC_UX_LP
AENC_VN: P500.2 R503.2
AENC_VN_LP: C504.2 D501.3(C1A2) R503.1 ; port AENC_VN_LP
AENC_WY: P500.1 R502.2
AENC_WY_LP: C503.2 D500.3(C1A2) R502.1 ; port AENC_WY_LP
AGPI_A: P502.1 R505.2
AGPI_A_LP: C506.2 D504.3(C1A2) R505.1 R507.1 ; port AGPI_A_LP
AGPI_B: P501.1 R506.2
AGPI_B_LP: C507.2 D505.3(C1A2) R506.1 R508.1 ; port AGPI_B_LP

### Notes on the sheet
- (near D503) VM ADC Filter
- (near C502) Current Inputs: Voltage divider for 3.3V Inputs (-3dB@194KHz)
- VM: MAX 80V supply voltage in current configuration

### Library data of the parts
C500 = C, 1 µF, 10 V, ± 10%, X5R, MC Series, 0603 [1608 Metric]: as C300 on sheet [3]_Output_Feedback
C501-C505 = C, 100 pF, 50 V, ± 5%, C0G / NP0, MC Series, 0603 [1608 Metric]: as C304 on sheet [3]_Output_Feedback
C506 C507 = C, 100 pF, 10 V, ± 1%, C0G / NP0, MCMT Series, 0603 [1608 Metric]: SMD Multilayer Ceramic Capacitor, 0603 [1608 Metric], 100 pF, 10 V, ± 1%, C0G / NP0, MCMT Series; MPN: MCMT18N101F100CT; Type: MLCC; VoltageRating: 10V; MF: MULTICOMP; Capacitance: 100pF
C508 = C, 10nF, 10 V, ± 10%, X7R, 0603: SMD Multilayer Ceramic Capacitor, 0603 [1608 Metric], 0.01 µF, 10 V, ± 10%, X7R, MCSH Series; MPN: MCSH18B103K100CT; Type: MLCC; VoltageRating: 10V; MF: MULTICOMP
D500-D505 = BAT54S: as D200 on sheet [2]_Communication_Inputs
P500 = Header 5: Header, 5-Pin
P501 P502 = Header 2: Header, 2-Pin
R500-R504 = R, 100 ohm, 50 V, 0603 [1608 Metric], 100 mW, ± 1%, MCWR Series: SMD Chip Resistor, Thick Film, 100 ohm, 50 V, 0603 [1608 Metric], 100 mW, ± 1%, MCWR Series; MPN: MCWR06X1000FTL; VoltageRating: 50V; Temp coefficient: *ppm; PowerRating: 100mW; MF: MULTICOMP
R505 R506 = R, 4 kohm, 150 V, 0805 [2012 Metric], 125 mW, ± 1%, CRCW Series: SMD Chip Resistor, Thick Film, 4 kohm, 150 V, 0805 [2012 Metric], 125 mW, ± 1%, CRCW Series; MPN: CRCW08054K00FKTA; VoltageRating: 150V; Temp coefficient: *ppm; PowerRating: 125mW; MF: VISHAY
R507 R508 = R, 1 kohm, 50 V, 0603 [1608 Metric], 63 mW, ± 1%, MC Series: SMD Chip Resistor, Thick Film, 1 kohm, 50 V, 0603 [1608 Metric], 100 mW, ± 0.5%, RE Series; MPN: MC0063W060311K; Precision: 1%; VoltageRating: 50V; Temp coefficient: *ppm; PowerRating: 63mW; MF: MULTICOMP
R509 = R, 1.5 kohm, 50 V, 0603 [1608 Metric], 100 mW, ± 1%, MCWR Series: SMD Chip Resistor, Thick Film, 1.5 kohm, 50 V, 0603 [1608 Metric], 100 mW, ± 1%, MCWR Series; MPN: MCWR06X1501FTL; VoltageRating: 50V; Temp coefficient: *ppm; PowerRating: 63mW; MF: MULTICOMP
R510 = R, 100 kohm, 50 V, 0603 [1608 Metric], 100 mW, ± 1%, MCWR Series: SMD Chip Resistor, Thick Film, 100 kohm, 50 V, 0603 [1608 Metric], 100 mW, ± 1%, MCWR Series; MPN: MCWR06X1003FTL; Temp coefficient: *ppm; MF: MULTICOMP

## Sheet [6]_PSU.SchDoc: PSU
size A4; DocumentNumber: 6; SheetNumber: 6; SheetTotal: 8
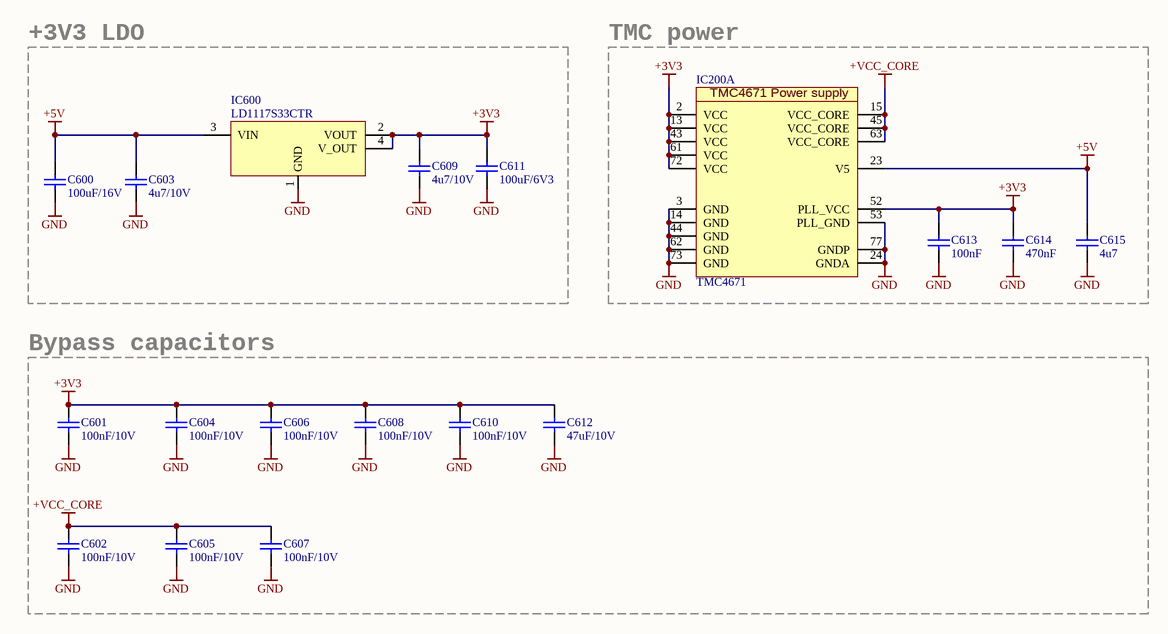
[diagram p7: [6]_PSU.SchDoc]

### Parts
C600  100uF/16V  [C1210]
C601  100nF/10V  [C0603]
C602  100nF/10V  [C0603]
C603  4u7/10V  [C0603]
C604  100nF/10V  [C0603]
C605  100nF/10V  [C0603]
C606  100nF/10V  [C0603]
C607  100nF/10V  [C0603]
C608  100nF/10V  [C0603]
C609  4u7/10V  [C0603]
C610  100nF/10V  [C0603]
C611  100uF/6V3  [C1210]
C612  47uF/10V  [C1206]
C613  100nF  [C0603]
C614  470nF  [C0603]
C615  4u7  [C0603]
IC200  TMC4671  [QFN40P1050X650X90_HS-77N]  (part A of 5)
IC600  LD1117S33CTR  [SOT230P700X180-4N]

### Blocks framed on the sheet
+3V3 LDO: C600 C603 C609 C611 IC600
TMC power: C613-C615 IC200
Bypass capacitors: C601 C602 C604-C608 C610 C612

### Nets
+3V3: C601.2 C604.2 C606.2 C608.2 C609.2 C610.2 C611.2 C612.2 C613.2 C614.1 IC200.2(VCC) IC200.13(VCC) IC200.43(VCC) IC200.52(PLL_VCC) IC200.61(VCC) IC200.72(VCC) IC600.2(VOUT) IC600.4(V_OUT)
+5V: C600.2 C603.2 C615.2 IC200.23(V5) IC600.3(VIN)
+VCC_CORE: C602.2 C605.2 C607.2 IC200.15(VCC_CORE) IC200.45(VCC_CORE) IC200.63(VCC_CORE)
GND: C600.1 C601.1 C602.1 C603.1 C604.1 C605.1 C606.1 C607.1 C608.1 C609.1 C610.1 C611.1 C612.1 C613.1 C614.2 C615.1 IC200.3(GND) IC200.14(GND) IC200.24(GNDA) IC200.44(GND) IC200.53(PLL_GND) IC200.62(GND) IC200.73(GND) IC200.77(GNDP) IC600.1(GND)

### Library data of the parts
C600 = C, 100 µF, 16 V, ± 20%, X5R, M Series, 1210: SMD Multilayer Ceramic Capacitor, 1210 [3225 Metric], 100 µF, 16 V, ± 20%, X5R, M Series; MPN: EMK325ABJ107MM-T; Type: MLCC; VoltageRating: 16V; MF: TAIYO YUDEN; Capacitance: 100uF
C601 C602 C604-C608 C610 = C, 0.1 µF, 10 V, ± 10%, X7R, 0603: as C200 on sheet [2]_Communication_Inputs
C603 C609 = C, 4.7 µF, 10 V, ± 10%, X5R, MC Series , 0603: SMD Multilayer Ceramic Capacitor, 0603 [1608 Metric], 4.7 µF, 10 V, ± 10%, X5R, MC Series; MPN: MC0603X475K100CT; Type: MLCC; VoltageRating: 10V; MF: MULTICOMP; Capacitance: 4u7
C611 = C, 100 µF, 6.3 V, ± 20%, X5R, GRM Series, 1210: SMD Multilayer Ceramic Capacitor, 1210 [3225 Metric], 100 µF, 6.3 V, ± 20%, X5R, GRM Series; MPN: GRM31CR60J107ME39L.; Type: MLCC; VoltageRating: 6V3; MF: MURATA; Capacitance: 100uF
C612 = C, 47 µF, 10 V, ± 20%, X7R, MC Series , 1206: SMD Multilayer Ceramic Capacitor, 1206 [3216 Metric], 47 µF, 10 V, ± 20%, X5R, GRM Series; MPN: GRM31CR61A476ME15L; Type: MLCC; VoltageRating: 10V; MF: MURATA; Capacitance: 47uF
C613 = C, 0.1 µF, 10 V, ± 10%, X7R, 0603: SMD Multilayer Ceramic Capacitor, 0603 [1608 Metric], 0.1 µF, 10 V, ± 10%, X7R, MC Series; MPN: MC0603B104K100CT; Type: MLCC; VoltageRating: 10V; MF: Multicomp
C614 = C, 0.47 µF, 16 V, ± 10%, X5R, MC Series, 0603 [1608 Metric]: SMD Multilayer Ceramic Capacitor, 0603 [1608 Metric], 0.47 µF, 16 V, ± 10%, X5R, MC Series; MPN: MC0603X474K160CT; Type: MLCC; Voltage rating: 16V; ComponentLinknDescription: Datasheet; MF: Multicomp
C615 = C, 4.7 µF, 10 V, ± 10%, X5R, MC Series , 0603: SMD Multilayer Ceramic Capacitor, 0603 [1608 Metric], 4.7 µF, 10 V, ± 10%, X5R, MC Series; MPN: MC0603X475K100CT; Type: MLCC; VoltageRating: 10V; MF: MULTICOMP
IC200 = TMC4671: MF: TRINAMIC
IC600 = LDO_LD1117S33CTR: Fixed LDO Voltage Regulator, 4.75V to 15V, 1.1V Dropout, 3.3Vout, 950mAout, SOT-223-4; MF: STMICROELECTRONICS

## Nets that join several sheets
+3V3: [1]_InterfaceConnectors (TP1.1), [2]_Communication_Inputs (7 pins), [3]_Output_Feedback (8 pins), [6]_PSU (18 pins)
+5V: [1]_InterfaceConnectors (P1.42 P2.42 TP2.1), [3]_Output_Feedback (20 pins), [4]_Output_Feedback_2 (5 pins), [5]_Analog_input_filters (8 pins), [6]_PSU (5 pins)
+VM: [1]_InterfaceConnectors (P1.1 P2.1), [5]_Analog_input_filters (R510.2)
GND: [1]_InterfaceConnectors (17 pins), [2]_Communication_Inputs (13 pins), [3]_Output_Feedback (28 pins), [4]_Output_Feedback_2 (6 pins), [5]_Analog_input_filters (21 pins), [6]_PSU (25 pins)
ADC_I0_LP: [4]_Output_Feedback_2 (IC200.16), [5]_Analog_input_filters (C501.2 R500.1)
ADC_I0_U: [1]_InterfaceConnectors (P2.15), [5]_Analog_input_filters (R500.2)
ADC_I1_LP: [4]_Output_Feedback_2 (IC200.18), [5]_Analog_input_filters (C502.2 R501.1)
ADC_I1_V: [1]_InterfaceConnectors (P2.14), [5]_Analog_input_filters (R501.2)
ADC_VM_LP: [4]_Output_Feedback_2 (IC200.20), [5]_Analog_input_filters (C508.2 D503.3 R509.1 R510.1)
AENC_UX_INN: [1]_InterfaceConnectors (TP11.1), [4]_Output_Feedback_2 (IC200.26 R404.1 R405.2)
AENC_UX_LP: [4]_Output_Feedback_2 (IC200.25), [5]_Analog_input_filters (C505.2 D502.3 R504.1)
AENC_VN_INN: [1]_InterfaceConnectors (TP12.1), [4]_Output_Feedback_2 (IC200.28 R402.1 R403.2)
AENC_VN_LP: [4]_Output_Feedback_2 (IC200.27), [5]_Analog_input_filters (C504.2 D501.3 R503.1)
AENC_WY_INN: [1]_InterfaceConnectors (TP13.1), [4]_Output_Feedback_2 (IC200.30 R400.1 R401.2)
AENC_WY_LP: [4]_Output_Feedback_2 (IC200.29), [5]_Analog_input_filters (C503.2 D500.3 R502.1)
AGPI_A_LP: [2]_Communication_Inputs (IC200.21), [5]_Analog_input_filters (C506.2 D504.3 R505.1 R507.1)
AGPI_B_LP: [2]_Communication_Inputs (IC200.22), [5]_Analog_input_filters (C507.2 D505.3 R506.1 R508.1)
CLK25: [1]_InterfaceConnectors (P1.23), [2]_Communication_Inputs (IC200.51 XTL200.3)
CS_CH0: [1]_InterfaceConnectors (P1.6), [2]_Communication_Inputs (IC201.1)
DBG_SPI_MISO: [1]_InterfaceConnectors (TP9.1), [2]_Communication_Inputs (IC200.4 P201.9)
DBG_SPI_MOSI: [1]_InterfaceConnectors (TP8.1), [2]_Communication_Inputs (IC200.1 P201.7)
DBG_SPI_nSCS: [1]_InterfaceConnectors (TP6.1), [2]_Communication_Inputs (IC200.75 P201.3)
DBG_SPI_SCK: [1]_InterfaceConnectors (TP7.1), [2]_Communication_Inputs (IC200.76 P201.5)
DBG_SPI_TRG: [1]_InterfaceConnectors (TP10.1), [2]_Communication_Inputs (IC200.5 P201.4)
EN_IN: [1]_InterfaceConnectors (P1.8), [2]_Communication_Inputs (IC200.55)
EN_OUT: [1]_InterfaceConnectors (P2.40), [2]_Communication_Inputs (IC200.32)
ENC1_A: [3]_Output_Feedback (IC300.2), [4]_Output_Feedback_2 (IC200.35)
ENC1_B: [3]_Output_Feedback (IC300.5), [4]_Output_Feedback_2 (IC200.34)
ENC1_N: [3]_Output_Feedback (IC300.7), [4]_Output_Feedback_2 (IC200.33)
ENC2_A: [3]_Output_Feedback (IC301.2), [4]_Output_Feedback_2 (IC200.64)
ENC2_B: [3]_Output_Feedback (IC301.5), [4]_Output_Feedback_2 (IC200.65)
ENC2_N: [3]_Output_Feedback (IC301.7), [4]_Output_Feedback_2 (IC200.66)
GPIO0: [1]_InterfaceConnectors (P1.35 TP3.1), [2]_Communication_Inputs (IC200.70)
GPIO1: [1]_InterfaceConnectors (P1.37 TP4.1), [2]_Communication_Inputs (IC200.71)
GPIO2: [1]_InterfaceConnectors (TP5.1), [2]_Communication_Inputs (IC200.74)
HALL_UX: [3]_Output_Feedback (IC302.2), [4]_Output_Feedback_2 (IC200.38)
HALL_V: [3]_Output_Feedback (IC302.5), [4]_Output_Feedback_2 (IC200.37)
HALL_WY: [3]_Output_Feedback (IC302.7), [4]_Output_Feedback_2 (IC200.36)
PWM_H_IDLE: [1]_InterfaceConnectors (P2.34), [4]_Output_Feedback_2 (IC200.59)
PWM_IN: [1]_InterfaceConnectors (P1.21), [2]_Communication_Inputs (D200.3 IC200.58 P202.1)
PWM_L_IDLE: [1]_InterfaceConnectors (P2.35), [4]_Output_Feedback_2 (IC200.60)
PWM_UX1_H: [1]_InterfaceConnectors (P2.18), [4]_Output_Feedback_2 (IC200.39)
PWM_UX1_L: [1]_InterfaceConnectors (P2.17), [4]_Output_Feedback_2 (IC200.40)
PWM_VX2_H: [1]_InterfaceConnectors (P2.20), [4]_Output_Feedback_2 (IC200.41)
PWM_VX2_L: [1]_InterfaceConnectors (P2.19), [4]_Output_Feedback_2 (IC200.42)
PWM_WY1_H: [1]_InterfaceConnectors (P2.22), [4]_Output_Feedback_2 (IC200.46)
PWM_WY1_L: [1]_InterfaceConnectors (P2.21), [4]_Output_Feedback_2 (IC200.47)
PWM_Y2_H: [1]_InterfaceConnectors (P2.23), [4]_Output_Feedback_2 (IC200.48)
PWM_Y2_L: [1]_InterfaceConnectors (P2.26), [4]_Output_Feedback_2 (IC200.49)
REF_H: [3]_Output_Feedback (IC303.5), [4]_Output_Feedback_2 (IC200.68)
REF_L: [3]_Output_Feedback (IC303.2), [4]_Output_Feedback_2 (IC200.67)
REF_R: [3]_Output_Feedback (IC303.7), [4]_Output_Feedback_2 (IC200.69)
SD_DIR: [1]_InterfaceConnectors (P1.18), [2]_Communication_Inputs (IC200.56)
SD_STP: [1]_InterfaceConnectors (P1.17), [2]_Communication_Inputs (IC200.57)
SPI_MISO: [1]_InterfaceConnectors (P1.33), [2]_Communication_Inputs (IC200.9 IC201.2)
SPI_MOSI: [1]_InterfaceConnectors (P1.32), [2]_Communication_Inputs (IC200.8 IC201.5)
SPI_nSCS: [1]_InterfaceConnectors (P1.30), [2]_Communication_Inputs (IC200.6)
SPI_SCK: [1]_InterfaceConnectors (P1.31), [2]_Communication_Inputs (IC200.7 IC201.6)
STATUS: [1]_InterfaceConnectors (P1.13), [2]_Communication_Inputs (IC200.12)
UART_RXD: [1]_InterfaceConnectors (P1.39), [2]_Communication_Inputs (IC200.10 P200.3)
UART_TXD: [1]_InterfaceConnectors (P1.40), [2]_Communication_Inputs (IC200.11 P200.2)

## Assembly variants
Variant of TMC4671-EVAL_V1_0: not fitted P200 P202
